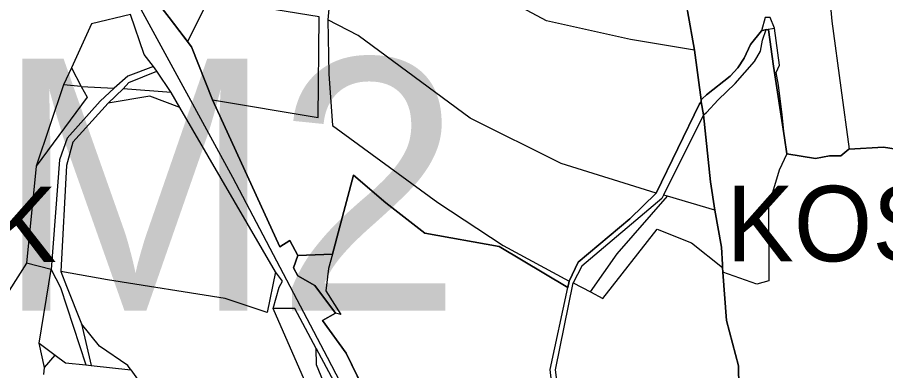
# Model space of a CAD drawing. Extents: x -706771 to -698463, y -971709 to -967107.
# Drawn here: x -703053 to -702363, y -970012 to -969731 of the extents above; entities that cross this region are included whole.
import ezdxf

# ---------------------------------------------------------------- set-up
doc = ezdxf.new("R2010")
doc.units = 0
for name, color, linetype in [('_KRAJINNY OKRSEK', 7, 'Continuous'), ('_KRAJINNY OKRSEK_popis', 7, 'Continuous'), ('Dráha_osa koleje', 7, 'Continuous'), ('Hranice katastralnich uzemi', 7, 'Continuous'), ('KN_Hranice_parcel', 7, 'Continuous'), ('Typ krajiny popis', 7, 'Continuous')]:
    doc.layers.add(name, color=color, linetype=linetype)

msp = doc.modelspace()

# ---------------------------------------------------------------- linework, layer by layer
at = {"layer": '_KRAJINNY OKRSEK'}
for p, q in [((-702457.79, -969740.89), (-702461.69, -969742.04)), ((-702456.14, -969741.08), (-702457.79, -969740.89)), ((-702898.09, -969796.67), (-702914.55, -969754.65)), ((-702914.55, -969754.65), (-702898.09, -969796.67)), ((-702480.43, -969771.34), (-702475.44, -969763.52)), ((-702486.48, -969778.01), (-702480.43, -969771.34)), ((-702505.43, -969792.69), (-702486.48, -969778.01)), ((-702844.46, -969913.42), (-702898.09, -969796.67)), ((-702898.09, -969796.67), (-702844.46, -969913.42)), ((-702508.85, -969795.89), (-702505.43, -969792.69)), ((-702510.78, -969799.9), (-702545.31, -969870.8)), ((-702392.33, -969836.05), (-702398.56, -969841.17)), ((-702398.56, -969841.17), (-702392.33, -969836.05)), ((-702392.33, -969836.05), (-702391.87, -969836.02)), ((-702391.87, -969836.02), (-702364.58, -969834.37)), ((-702398.56, -969841.17), (-702407.7, -969841.14)), ((-702407.7, -969841.14), (-702398.56, -969841.17)), ((-702802.71, -969919.44), (-702786.02, -969856.63)), ((-702786.02, -969856.63), (-702760.15, -969878.48)), ((-702545.31, -969870.8), (-702566.26, -969891.26)), ((-702566.26, -969891.26), (-702607.46, -969925.8)), ((-702836.6, -969908.44), (-702844.46, -969913.42)), ((-702844.46, -969913.42), (-702836.6, -969908.44)), ((-702830.27, -969920.52), (-702836.6, -969908.44)), ((-702836.6, -969908.44), (-702830.27, -969920.52)), ((-702670.05, -969913.25), (-702615.63, -969945.77)), ((-702830.27, -969920.52), (-702833.59, -969930.29)), ((-702802.71, -969919.44), (-702830.27, -969920.52)), ((-702830.27, -969920.52), (-702802.71, -969919.44)), ((-702607.46, -969925.8), (-702614.56, -969940.73)), ((-702833.59, -969930.29), (-702830.05, -969936.63)), ((-702615.63, -969945.77), (-702614.56, -969940.73)), ((-702791.68, -969997.89), (-702709.14, -970168.26))]:
    msp.add_line(p, q, dxfattribs=at)
for points in [[(-702914.55, -969754.65), (-702932.52, -969731.2), (-702941.63, -969719.32)], [(-702941.63, -969719.32), (-702932.52, -969731.2), (-702914.55, -969754.65)], [(-702461.69, -969742.04), (-702457.79, -969740.89), (-702456.14, -969741.08), (-702452.17, -969769.95), (-702443.27, -969826.9), (-702441.38, -969839.73)], [(-702441.38, -969839.73), (-702443.27, -969826.9), (-702452.17, -969769.95), (-702456.14, -969741.08)], [(-702461.69, -969742.04), (-702470.34, -969752.8), (-702475.44, -969763.52)], [(-702475.44, -969763.52), (-702470.34, -969752.8), (-702461.69, -969742.04)], [(-702475.44, -969763.52), (-702480.43, -969771.34), (-702486.48, -969778.01), (-702505.43, -969792.69)], [(-702614.56, -969940.73), (-702607.46, -969925.8), (-702566.26, -969891.26), (-702545.31, -969870.8), (-702510.78, -969799.9), (-702509.47, -969798.3), (-702509.66, -969796.84), (-702508.85, -969795.89)], [(-702509.66, -969796.84), (-702509.47, -969798.3), (-702510.78, -969799.9)], [(-702505.43, -969792.69), (-702508.85, -969795.89), (-702509.66, -969796.84)], [(-702278.11, -969813.56), (-702296.64, -969826.47), (-702315.68, -969831.21), (-702334.2, -969835.47), (-702348.03, -969836.96), (-702364.58, -969834.37), (-702391.87, -969836.02), (-702392.33, -969836.05)], [(-702364.58, -969834.37), (-702348.03, -969836.96), (-702334.2, -969835.47), (-702315.68, -969831.21), (-702296.64, -969826.47)], [(-702407.7, -969841.14), (-702418.7, -969843.4), (-702441.38, -969839.73)], [(-702441.38, -969839.73), (-702418.7, -969843.4), (-702407.7, -969841.14)], [(-702614.56, -969940.73), (-702615.63, -969945.77), (-702670.05, -969913.25), (-702729.12, -969902.79), (-702760.15, -969878.48), (-702786.02, -969856.63), (-702802.71, -969919.44)], [(-702760.15, -969878.48), (-702729.12, -969902.79), (-702670.05, -969913.25)], [(-702709.14, -970168.26), (-702791.68, -969997.89), (-702810.52, -969971.96), (-702800.07, -969966.26), (-702816.66, -969944.13), (-702830.05, -969936.63), (-702833.59, -969930.29), (-702830.27, -969920.52)], [(-702830.05, -969936.63), (-702816.66, -969944.13), (-702800.07, -969966.26)], [(-702800.07, -969966.26), (-702810.52, -969971.96), (-702791.68, -969997.89)]]:
    msp.add_lwpolyline(points, dxfattribs=at)
at = {"layer": 'Dráha_osa koleje'}
msp.add_lwpolyline([(-702235.85, -970431.18), (-702397.68, -970414.14), (-702443.61, -970405.89), (-702497.3, -970388.6), (-702539.88, -970362.78), (-702587.63, -970325.88), (-702624.8, -970294.64), (-702653.7, -970264.71), (-702684.93, -970222.65), (-702730.35, -970148.06), (-702806.49, -970001.46), (-702881.85, -969858.48), (-702956.18, -969721.94), (-703010.64, -969614.58), (-703025.88, -969585.12), (-703032.47, -969572.8), (-703039.3, -969560.22), (-703048.42, -969544.88), (-703057.61, -969531.35)], dxfattribs=at)
at = {"layer": 'Hranice katastralnich uzemi'}
for points in [[(-702479.82, -970196.28), (-702478.97, -970187.36), (-702478.77, -970185.26), (-702477.63, -970173.36), (-702477.6, -970173.02), (-702476.14, -970157.71), (-702474.02, -970119.82), (-702477.8, -970082.42), (-702478.78, -970072.03), (-702479.26, -970041.25), (-702480.02, -970008.07), (-702489.56, -969971.94), (-702492.35, -969933.77), (-702492.63, -969929.93), (-702492.74, -969927.55), (-702493.52, -969913.71), (-702498.61, -969884.5), (-702502.22, -969861.79), (-702507.77, -969808.53), (-702509.47, -969798.3), (-702509.66, -969796.84), (-702514.86, -969757.16), (-702520.4, -969726.09)], [(-702520.4, -969726.09), (-702514.86, -969757.16), (-702509.66, -969796.84), (-702509.47, -969798.3), (-702507.77, -969808.53), (-702502.22, -969861.79), (-702498.61, -969884.5), (-702493.52, -969913.71), (-702492.74, -969927.55), (-702492.63, -969929.93), (-702492.35, -969933.77), (-702489.56, -969971.94), (-702480.02, -970008.07), (-702479.26, -970041.25), (-702478.78, -970072.03), (-702477.8, -970082.42), (-702474.02, -970119.82)]]:
    msp.add_lwpolyline(points, dxfattribs=at)
at = {"layer": 'KN_Hranice_parcel'}
for p, q in [((-702799.61, -969657.54), (-702806.36, -969733.07)), ((-702903.79, -969722.62), (-702917.79, -969750.42)), ((-702932.52, -969731.2), (-702917.79, -969750.42)), ((-702509.66, -969796.84), (-702514.86, -969757.16)), ((-702509.66, -969796.84), (-702514.86, -969757.16)), ((-703010.13, -969771.23), (-703016.39, -969784.81)), ((-703010.13, -969771.23), (-703002.27, -969786.09)), ((-702942.22, -969774.09), (-702944.78, -969770.38)), ((-702930.8, -969791.02), (-702942.22, -969774.09)), ((-703016.39, -969784.81), (-703038.04, -969849.54)), ((-703002.27, -969786.09), (-703016.39, -969784.81)), ((-703002.27, -969786.09), (-702976.11, -969787.53)), ((-702980.96, -969799.49), (-702969.05, -969787.92)), ((-702930.8, -969791.02), (-702969.05, -969787.92)), ((-702923.89, -969802.96), (-702930.8, -969791.02)), ((-702509.47, -969798.3), (-702509.66, -969796.84)), ((-702509.47, -969798.3), (-702509.66, -969796.84)), ((-702847.98, -969933.34), (-702923.89, -969802.96)), ((-702507.77, -969808.53), (-702509.47, -969798.3)), ((-702507.77, -969808.53), (-702509.47, -969798.3)), ((-702507.77, -969808.53), (-702539.57, -969872.45)), ((-703038.04, -969849.54), (-703045.66, -969926.4)), ((-702536.39, -969873.38), (-702539.57, -969872.45)), ((-702498.61, -969884.5), (-702536.39, -969873.38)), ((-702830.27, -969920.52), (-702802.71, -969919.44)), ((-703026.15, -969931.51), (-703045.66, -969926.4)), ((-702492.63, -969929.93), (-702492.74, -969927.55)), ((-702492.63, -969929.93), (-702492.74, -969927.55)), ((-703035.85, -969990.05), (-703026.15, -969931.51)), ((-702492.35, -969933.77), (-702492.63, -969929.93)), ((-702492.35, -969933.77), (-702492.63, -969929.93)), ((-702615.63, -969945.77), (-702614.56, -969940.73)), ((-702611.22, -969942.17), (-702597.66, -969949.36)), ((-702816.16, -970039.25), (-702849.71, -969962.42)), ((-703002.2, -969974.62), (-702994.37, -970007.81)), ((-703031.6, -970009.47), (-703035.85, -969990.05)), ((-703035.85, -969990.05), (-703023.07, -969999.47)), ((-703031.6, -970009.47), (-703023.07, -969999.47)), ((-703031.9, -970014.84), (-703031.6, -970009.47)), ((-702998.67, -970007.34), (-702994.37, -970007.81)), ((-702994.37, -970007.81), (-702962.75, -970011.28)), ((-702962.75, -970011.28), (-702941.13, -970041.38))]:
    msp.add_line(p, q, dxfattribs=at)
for points in [[(-702285.19, -969219.7), (-702286.57, -969223.52), (-702311.7, -969279.26), (-702318.49, -969289.7), (-702330.02, -969309.33), (-702347.28, -969339.76), (-702351.31, -969346.93), (-702373.81, -969389.56), (-702378.85, -969399.35), (-702395.04, -969441.63), (-702397.52, -969450.6), (-702405.04, -969488.2), (-702409.78, -969533.62), (-702410.11, -969598.7), (-702410.23, -969661.43), (-702409.03, -969699.01), (-702405.7, -969734.35), (-702398.47, -969787.22), (-702391.87, -969836.02)], [(-702514.86, -969757.16), (-702520.4, -969726.09), (-702531.48, -969676.36), (-702547.47, -969592.46), (-702557.22, -969538.47)], [(-702514.86, -969757.16), (-702520.4, -969726.09), (-702531.48, -969676.36), (-702547.47, -969592.46), (-702557.22, -969538.47)], [(-702514.86, -969757.16), (-702565.75, -969748.74), (-702632.4, -969733.88), (-702749.66, -969671.1), (-702761.76, -969666.37)], [(-702898.09, -969796.67), (-702814.03, -969810.82), (-702813.26, -969730.75), (-702847.63, -969725.14)], [(-702963.15, -969728.94), (-702994.01, -969736.23), (-703010.13, -969771.23)], [(-702944.78, -969770.38), (-702946.64, -969767.85), (-702952.14, -969760.74), (-702963.15, -969728.94)], [(-702545.31, -969870.8), (-702620.88, -969847.28), (-702693.25, -969811.4), (-702782.11, -969745.62), (-702806.36, -969733.07)], [(-702806.36, -969733.07), (-702805.48, -969776.16), (-702802.48, -969817.08), (-702718.74, -969878.2), (-702667, -969912.45), (-702614.56, -969940.73)], [(-702451.27, -969739.76), (-702454.77, -969731.35), (-702458.67, -969731.25), (-702461.69, -969742.04), (-702470.34, -969752.8), (-702475.44, -969763.52), (-702480.43, -969771.34), (-702486.48, -969778.01), (-702505.43, -969792.69), (-702508.85, -969795.89), (-702509.66, -969796.84)], [(-702507.77, -969808.53), (-702505.26, -969806.78), (-702496.02, -969796.78), (-702482.63, -969783.65), (-702474.91, -969775.08), (-702467.32, -969766.3), (-702462.3, -969758.13), (-702460.76, -969749.35), (-702457.79, -969740.89), (-702451.27, -969739.76)], [(-702441.38, -969839.73), (-702443.27, -969826.9), (-702445.11, -969808.62), (-702448.04, -969785.13), (-702450.1, -969775.04), (-702447.22, -969769.27), (-702451.27, -969739.76)], [(-702917.79, -969750.42), (-702914.55, -969754.65), (-702898.09, -969796.67)], [(-702944.78, -969770.38), (-702965.14, -969777.98), (-702976.11, -969787.53)], [(-702969.05, -969787.92), (-702964.49, -969783), (-702942.22, -969774.09)], [(-703002.27, -969786.09), (-702997.69, -969794.68), (-703038.04, -969849.54)], [(-702976.11, -969787.53), (-702987.33, -969797.7), (-703013.47, -969827.29), (-703019.57, -969844.37), (-703026.15, -969931.51)], [(-702923.89, -969802.96), (-702947.66, -969793.88), (-702980.96, -969799.49)], [(-702898.09, -969796.67), (-702844.46, -969913.42), (-702836.6, -969908.44), (-702830.27, -969920.52)], [(-702980.96, -969799.49), (-703008.84, -969830.48), (-703014, -969848.96), (-703018.63, -969933.07)], [(-702545.31, -969870.8), (-702510.78, -969799.9), (-702509.47, -969798.3)], [(-702498.61, -969884.5), (-702502.22, -969861.79), (-702507.77, -969808.53)], [(-702498.61, -969884.5), (-702502.22, -969861.79), (-702507.77, -969808.53)], [(-702391.87, -969836.02), (-702364.58, -969834.37), (-702348.03, -969836.96), (-702334.2, -969835.47), (-702320.33, -969832.37), (-702315.68, -969831.21)], [(-702391.87, -969836.02), (-702392.33, -969836.05), (-702398.56, -969841.17), (-702407.7, -969841.14), (-702418.7, -969843.4), (-702441.38, -969839.73)], [(-702441.38, -969839.73), (-702447.63, -969852.74), (-702456, -969880.87), (-702455.9, -969940.55), (-702465.3, -969943.31), (-702492.35, -969933.77)], [(-702615.63, -969945.77), (-702670.05, -969913.25), (-702729.12, -969902.79), (-702760.15, -969878.48), (-702786.02, -969856.63), (-702802.71, -969919.44)], [(-702614.56, -969940.73), (-702607.46, -969925.8), (-702566.26, -969891.26), (-702545.31, -969870.8)], [(-702539.57, -969872.45), (-702540.92, -969875.24), (-702604.5, -969928.84), (-702611.22, -969942.17)], [(-702597.66, -969949.36), (-702576.45, -969919.15), (-702536.39, -969873.38)], [(-702492.74, -969927.55), (-702493.52, -969913.71), (-702498.61, -969884.5)], [(-702492.74, -969927.55), (-702493.52, -969913.71), (-702498.61, -969884.5)], [(-702597.66, -969949.36), (-702587.62, -969954.68), (-702544.56, -969899.37), (-702517.15, -969910.45), (-702492.63, -969929.93)], [(-702830.27, -969920.52), (-702833.59, -969930.29), (-702830.05, -969936.63), (-702816.66, -969944.13), (-702800.07, -969966.26)], [(-702802.71, -969919.44), (-702805.71, -969930.74), (-702807.88, -969948.45), (-702795.96, -969967.34), (-702800.07, -969966.26)], [(-703045.66, -969926.4), (-703073.71, -969969.99), (-703078.62, -970038.01)], [(-703026.15, -969931.51), (-703018.82, -969945.82), (-702998.67, -970007.34)], [(-702847.98, -969933.34), (-702854.4, -969965.59), (-702887.82, -969954.54), (-702981.29, -969939.73), (-703018.63, -969933.07)], [(-703018.63, -969933.07), (-703014.05, -969944.83), (-703002.2, -969974.62)], [(-702849.71, -969962.42), (-702845, -969945.44), (-702842.35, -969940.73), (-702847.98, -969933.34)], [(-702476.14, -970157.71), (-702474.02, -970119.82), (-702477.8, -970082.42), (-702478.78, -970072.03), (-702479.26, -970041.25), (-702480.02, -970008.07), (-702489.56, -969971.94), (-702492.35, -969933.77)], [(-702476.14, -970157.71), (-702474.02, -970119.82), (-702477.8, -970082.42), (-702478.78, -970072.03), (-702479.26, -970041.25), (-702480.02, -970008.07), (-702489.56, -969971.94), (-702492.35, -969933.77)], [(-702478.77, -970185.26), (-702479.41, -970178.47), (-702502.37, -970168.75), (-702535.32, -970151.95), (-702551.89, -970130.8), (-702585.16, -970121.52), (-702615.94, -970107.76), (-702624.48, -970054.71), (-702629.46, -970011.04), (-702615.63, -969945.77)], [(-702501.01, -970165.86), (-702532.18, -970149.78), (-702549.64, -970126.84), (-702584.34, -970117.68), (-702612.79, -970105.16), (-702619.77, -970054.64), (-702625.32, -970011.26), (-702611.22, -969942.17)], [(-702815.51, -969994.34), (-702832.4, -969962.42), (-702849.71, -969962.42)], [(-702800.07, -969966.26), (-702810.52, -969971.96), (-702791.68, -969997.89), (-702709.14, -970168.26), (-702693.03, -970183.25), (-702681.82, -970200.08), (-702677.4, -970215.1), (-702666.82, -970223.33), (-702647.17, -970244.74), (-702626.57, -970275.28), (-702583.03, -970320.36), (-702551.99, -970345.34), (-702529.87, -970359.56), (-702498.64, -970376.32), (-702483.6, -970382.37), (-702470.15, -970385.24)], [(-702962.75, -970011.28), (-702965.33, -970007.68), (-702987.72, -969992.32), (-703002.2, -969974.62)], [(-702816.16, -970039.25), (-702805.54, -970031.06), (-702815.34, -970007.33), (-702815.51, -969994.34)], [(-702815.51, -969994.34), (-702724.75, -970163.8), (-702723.55, -970175.21), (-702716.86, -970194.93), (-702711.34, -970204.85), (-702693.88, -970218.53), (-702671.45, -970244.87), (-702639.26, -970279.81), (-702605.42, -970314.51), (-702589.2, -970329.23), (-702576, -970342.86), (-702534.94, -970369.18), (-702540.61, -970392.58), (-702527.61, -970404.52), (-702503.06, -970417.06), (-702488.09, -970412.27), (-702472.32, -970403.68), (-702465.64, -970405.87)], [(-703023.07, -969999.47), (-703014.79, -970005.58), (-702998.67, -970007.34)]]:
    msp.add_lwpolyline(points, dxfattribs=at)

# ---------------------------------------------------------------- texts
at = {"layer": '_KRAJINNY OKRSEK_popis'}
for s, p in [('KADAŠÁK', (-703400.72, -969925.68)), ('KOSTELNÍ VRCH', (-702489.47, -969925.05))]:
    msp.add_text(s, height=60, dxfattribs=at).set_placement(p)
at = {"layer": 'Typ krajiny popis'}
msp.add_text('5M2', height=200, dxfattribs=at).set_placement((-703219.76, -969964.11))

doc.saveas('drawing.dxf')
